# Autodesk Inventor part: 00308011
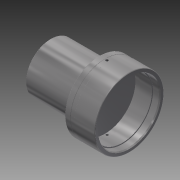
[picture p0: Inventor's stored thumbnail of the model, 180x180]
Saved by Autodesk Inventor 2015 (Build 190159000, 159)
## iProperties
Created: 2018-06
Part Number: 00308011
Material: Acciaio inossidabile
Document SubType Name: Modeling
Designer: stagistacad
Density: 8 g/cm^3
Appearance: Semilucidato
Author: stagistacad
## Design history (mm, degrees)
sketch "Schizzo1"
  geometry: L1 (32.289, 109.286)-(153.589, 109.286); L2 (169.289, 258.786)-(179.289, 258.786); L3 (169.289, 84.786)-(179.289, 84.786); L4 (32.289, 234.286)-(31.289, 233.286); L5 (32.289, 109.286)-(31.289, 110.286); L6 (32.289, 234.286)-(153.589, 234.286); L7 (156.789, 259.286)-(168.789, 259.286); L8 (31.289, 233.286)-(31.289, 110.286); L9 (227.789, 94.286)-(230.789, 92.554); L10 (156.789, 84.286)-(168.789, 84.286); L11 (154.789, 257.286)-(154.789, 235.486); L12 (168.789, 259.286)-(169.289, 258.786); L13 (168.789, 84.286)-(169.289, 84.786); L14 (179.789, 259.286)-(179.289, 258.786); L15 (179.789, 84.286)-(179.289, 84.786); L16 (179.789, 259.286)-(228.789, 259.286); L17 (179.789, 84.286)-(228.789, 84.286); L18 (230.789, 257.286)-(230.789, 86.286); L19 (154.789, 108.086)-(154.789, 86.286); L20 (169.289, 248.286)-(182.289, 248.286); L21 (169.289, 95.286)-(182.289, 95.286); L22 (169.289, 248.286)-(169.289, 95.286); L23 (182.289, 248.286)-(182.289, 95.286); L24 (182.289, 246.786)-(212.789, 246.786); L25 (182.289, 96.786)-(212.789, 96.786); L26 (183.289, 244.286)-(211.789, 244.286); L27 (183.289, 99.286)-(211.789, 99.286); L28 (182.289, 246.786)-(182.289, 96.786); L29 (212.789, 246.786)-(212.789, 96.786); L30 (183.289, 244.286)-(183.289, 99.286); L31 (183.289, 244.286)-(182.289, 245.286); L32 (183.289, 99.286)-(182.289, 98.286); L33 (211.789, 244.286)-(211.789, 99.286); L34 (211.789, 244.286)-(212.789, 245.286); L35 (211.789, 99.286)-(212.789, 98.286); L36 (213.189, 249.286)-(227.789, 249.286); L37 (213.189, 94.286)-(227.789, 94.286); L38 (212.789, 248.886)-(212.789, 94.686); L39 (230.789, 251.018)-(230.789, 92.554); L40 (227.789, 249.286)-(227.789, 94.286); L41 (227.789, 249.286)-(230.789, 251.018); L42 (24.289, 171.786)-(237.789, 171.786); L43 (175.289, 96.786)-(219.789, 96.786); L44 (175.289, 246.786)-(219.789, 246.786); L45 (37.789, 171.786)-(36.879, 170.211); L46 (36.879, 170.211)-(36.879, 173.361); L47 (34.363, 170.211)-(34.363, 173.361); L48 (31.289, 168.436)-(34.363, 170.211); L49 (36.879, 170.211)-(34.363, 170.211); L50 (31.289, 175.136)-(34.363, 173.361); L51 (28.289, 171.786)-(40.789, 171.786); L52 (36.879, 173.361)-(34.363, 173.361); L53 (37.789, 171.786)-(36.879, 173.361); L54 (162.789, 171.786)-(163.698, 173.361); L55 (163.698, 173.361)-(163.698, 170.211); L56 (166.214, 173.361)-(166.214, 170.211); L57 (169.289, 175.136)-(166.214, 173.361); L58 (163.698, 173.361)-(166.214, 173.361); L59 (169.289, 168.436)-(166.214, 170.211); L60 (172.289, 171.786)-(159.789, 171.786); L61 (163.698, 170.211)-(166.214, 170.211); L62 (162.789, 171.786)-(163.698, 170.211); L63 (174.289, 240.866)-(174.289, 263.286); L64 (176.747, 258.386)-(171.83, 258.386)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; A1 r 1.2 centre (153.589, 235.486) between (153.589, 234.286) and (154.789, 235.486); A2 r 1.2 centre (153.589, 108.086) between (154.789, 108.086) and (153.589, 109.286); A3 r 2 centre (156.789, 257.286) between (156.789, 259.286) and (154.789, 257.286); A4 r 2 centre (156.789, 86.286) between (154.789, 86.286) and (156.789, 84.286); A5 r 2 centre (228.789, 257.286) between (230.789, 257.286) and (228.789, 259.286); A6 r 2 centre (228.789, 86.286) between (228.789, 84.286) and (230.789, 86.286); A7 r 0.4 centre (213.189, 248.886) between (213.189, 249.286) and (212.789, 248.886); A8 r 0.4 centre (213.189, 94.686) between (212.789, 94.686) and (213.189, 94.286)
  constraints: 188 end point, 27 point on line, 16 point on circle, 8 centre point, 8 collinear, 2 midpoint, 1 horizontal, 1 parallel, 1 perpendicular
node "Piano di lavoro1"
revolve "Rivoluzione2" stored, may be unused: angle "d15" = 90 deg
node "Piano di lavoro2"
sketch "Schizzo4"
  geometry: L1 (179.289, 258.786)-(179.289, 84.786) reference; L2 (169.289, 258.786)-(169.289, 84.786) reference; L3 (169.289, 258.786)-(169.289, 84.786) reference; L4 (169.289, 171.786)-(179.289, 171.786); C1 r 3 at (174.289, 171.786); 1 further point
  constraints: 3 midpoint, 2 end point, 1 centre point
  dimensions: "d17" = 6 diameter of C1
extrude "Estrusione2" cut sketch "Schizzo4" distance "d18" = 1000; taper "d19" = 0 deg
chamfer "Smusso3" distance "d20" = 0.69; stored, may be unused: second distance "d21" = 0.4, angle "d22" = 45 deg
chamfer "Smusso4" distance "d23" = 0.69; stored, may be unused: second distance "d24" = 0.4, angle "d25" = 45 deg
feature "Filettatura3" dims "d26" = 7.6, "d27" = 0
feature "Filettatura4" dims "d28" = 7.6, "d29" = 0
node "Solido2"
node "Linea chiusa proiettata2"
other parameters: "d1" = 59.5, "d16" = 87
